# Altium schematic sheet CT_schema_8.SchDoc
size 371 x 336 mm
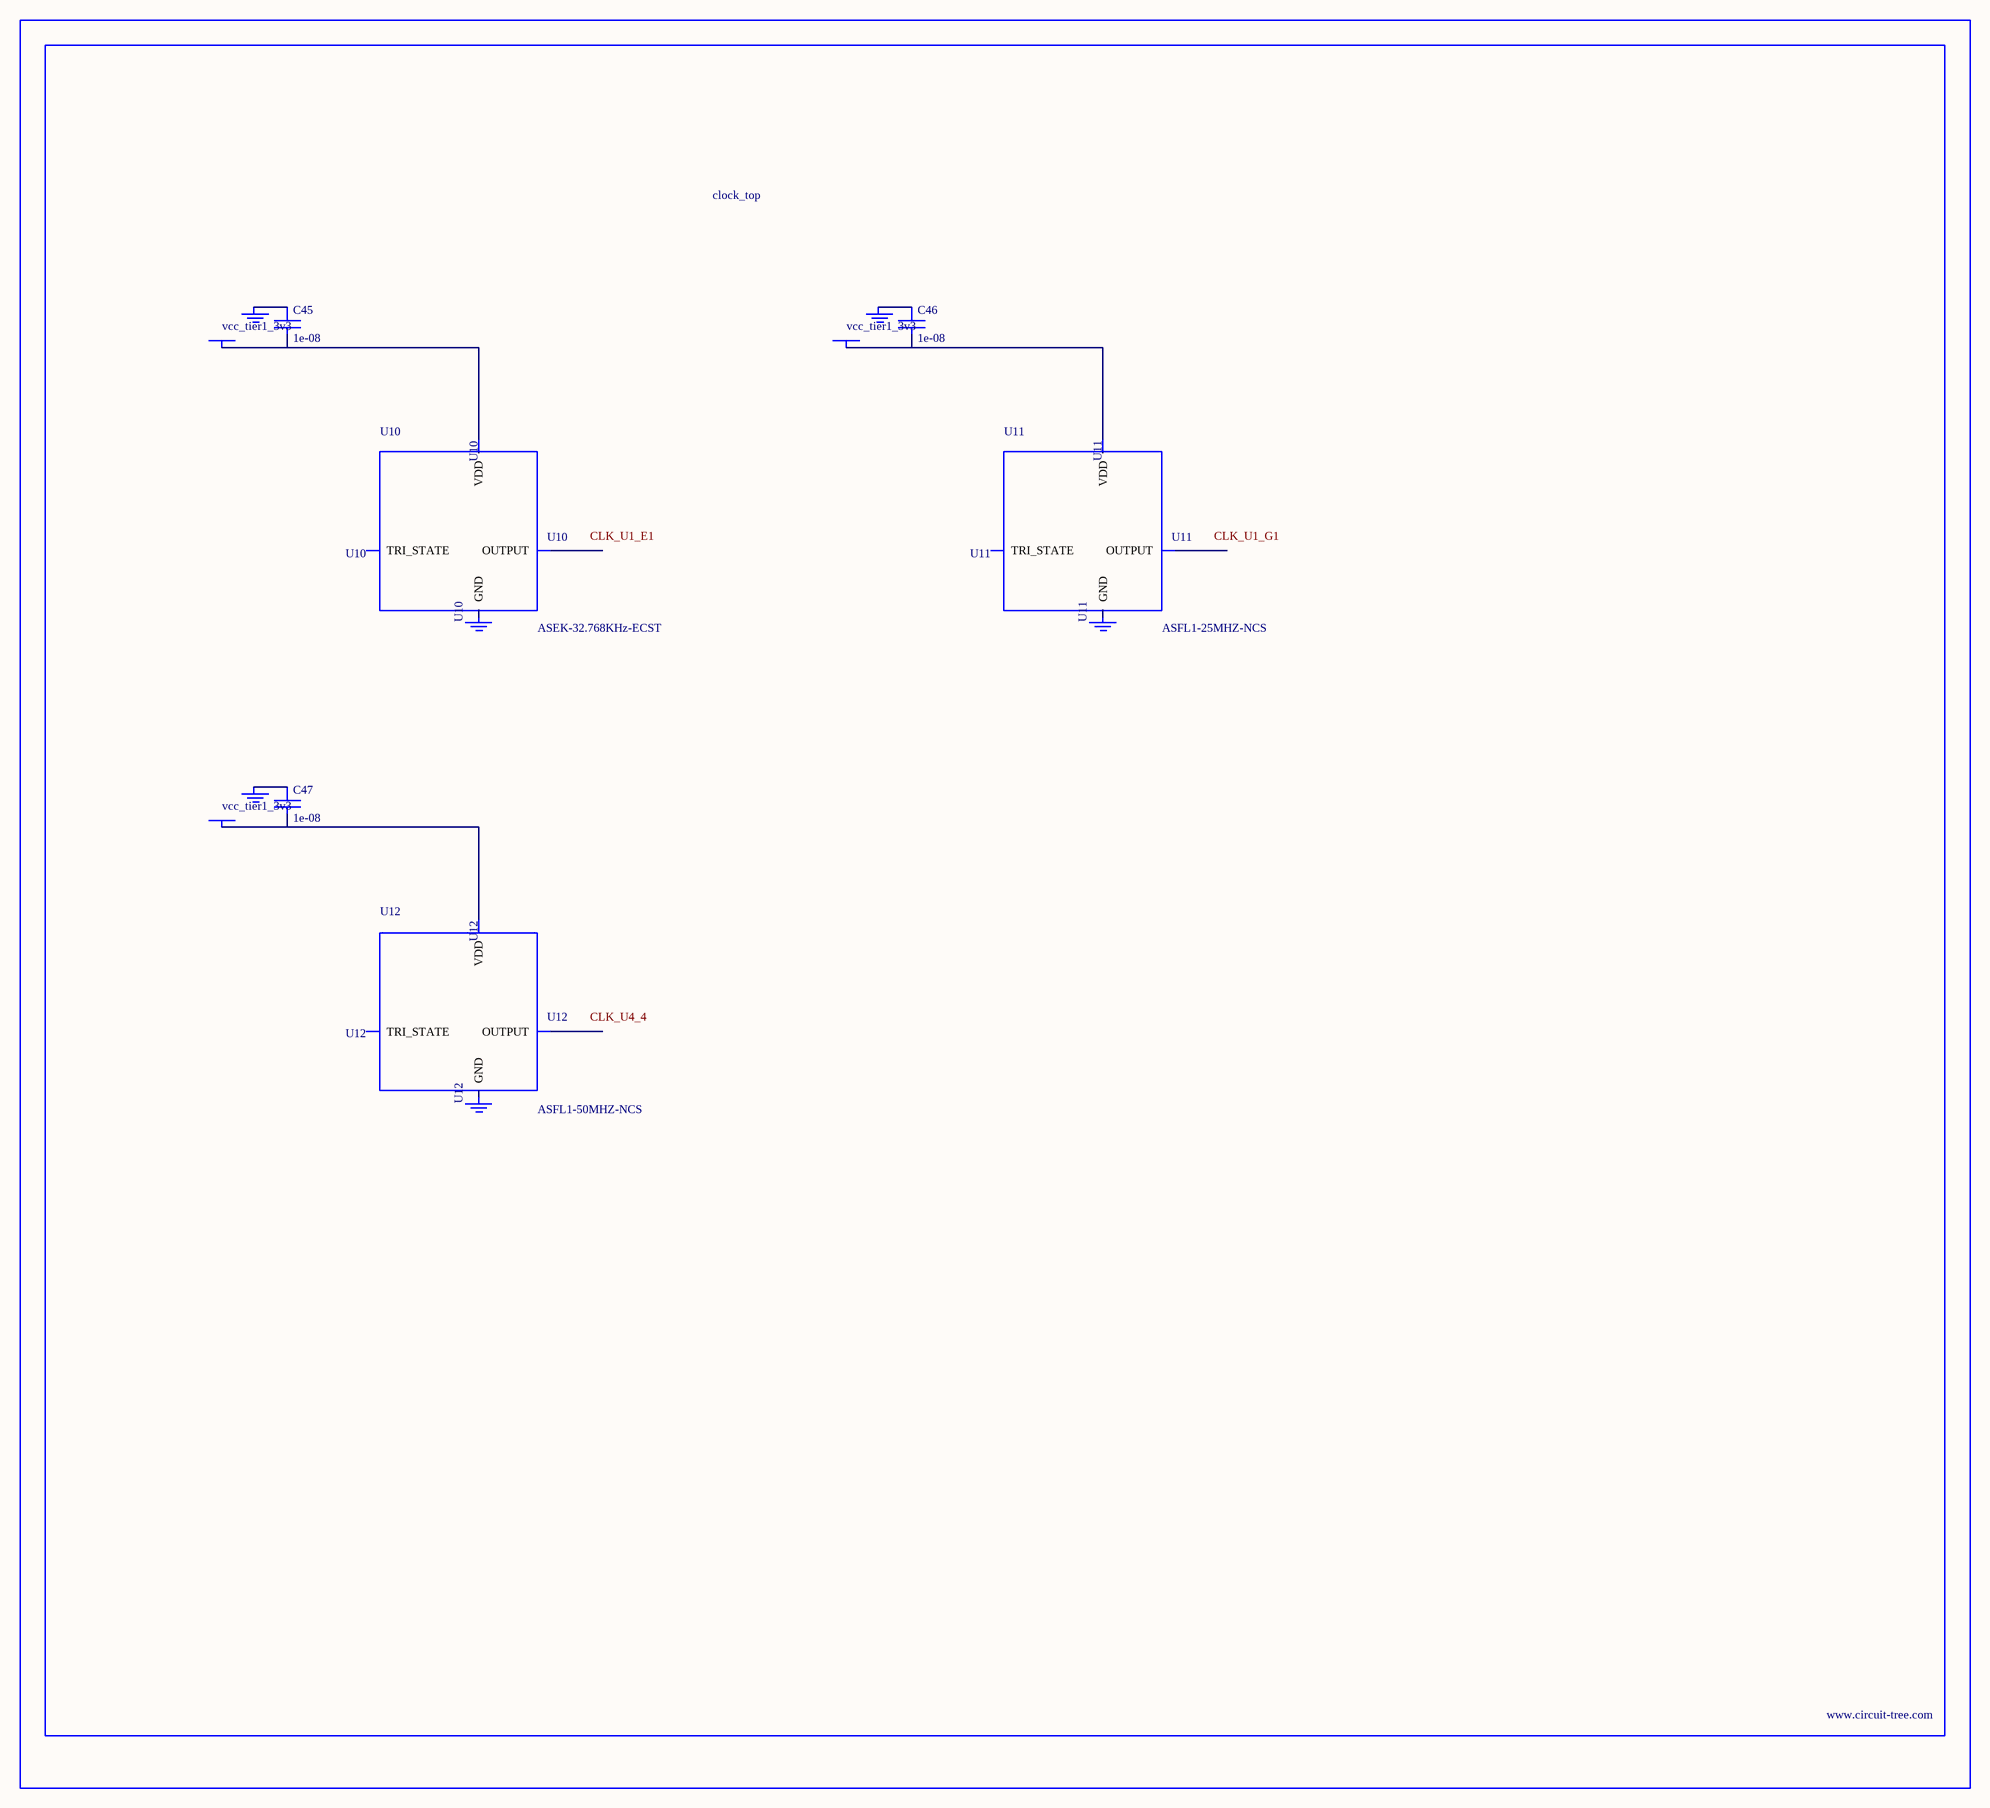
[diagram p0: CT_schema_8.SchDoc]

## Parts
BORDER7  (no value)
C45  1e-08  [C0402]
C46  1e-08  [C0402]
C47  1e-08  [C0402]
GND_INSTANCE_7_0  (no value)
GND_INSTANCE_7_1  (no value)
GND_INSTANCE_7_2  (no value)
GND_INSTANCE_7_3  (no value)
GND_INSTANCE_7_4  (no value)
GND_INSTANCE_7_5  (no value)
POWER_INSTANCE_7_0  vcc_tier1_3v3
POWER_INSTANCE_7_1  vcc_tier1_3v3
POWER_INSTANCE_7_2  vcc_tier1_3v3
U10  ASEK-32.768KHz-ECST  [ASEK]
U11  ASFL1-25MHZ-NCS  [ASFL1]
U12  ASFL1-50MHZ-NCS  [ASFL1]

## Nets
NetC45_1: C45.1 GND_INSTANCE_7_0.0(GND)
NetC45_2: C45.2 POWER_INSTANCE_7_0.0(PWR) U10.4(VDD)
NetC46_1: C46.1 GND_INSTANCE_7_2.0(GND)
NetC46_2: C46.2 POWER_INSTANCE_7_1.0(PWR) U11.4(VDD)
NetC47_1: C47.1 GND_INSTANCE_7_4.0(GND)
NetC47_2: C47.2 POWER_INSTANCE_7_2.0(PWR) U12.4(VDD)

Not connected (* = marked no-connect by the designer): GND_INSTANCE_7_1 0(GND); GND_INSTANCE_7_3 0(GND); GND_INSTANCE_7_5 0(GND); U10 1(TRI_STATE) 2(GND) 3(OUTPUT); U11 1(TRI_STATE) 2(GND) 3(OUTPUT); U12 1(TRI_STATE) 2(GND) 3(OUTPUT)

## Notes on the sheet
- Labels drawn without touching a wire or pin: CLK_U1_E1, CLK_U1_G1, CLK_U4_4

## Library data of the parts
BORDER7 = BORDER_PAGE7
C45-C47 = C0402C103K3RAC
GND_INSTANCE_7_0-GND_INSTANCE_7_5 = GND
POWER_INSTANCE_7_0-POWER_INSTANCE_7_2 = PWR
